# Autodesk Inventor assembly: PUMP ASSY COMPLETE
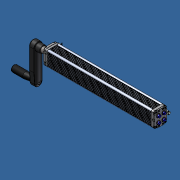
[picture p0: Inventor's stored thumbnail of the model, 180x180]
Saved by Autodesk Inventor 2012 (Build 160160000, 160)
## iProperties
Created: 2013-11
Part Number: PUMP ASSY COMPLETE
Document SubType Name: Assembly
Designer: Admin
Author: Admin
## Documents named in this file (4)
- C:\Andys Backup Data\ANDY'S INVENTOR\INVENTOR LIBRARIES\PARTS LIBRARY\HYDRAULIC VERTICAL ADJUSTMENT\27.9001Telescoping Twin Leg System\PUMP ASSY COMPLETE.iam
- C:\Andys Backup Data\ANDY'S INVENTOR\INVENTOR LIBRARIES\PARTS LIBRARY\HYDRAULIC VERTICAL ADJUSTMENT\27.9001Telescoping Twin Leg System\SUBCOMPONENTS\Qxx18_crank pump\Qxx18_crank.iam
- C:\Andys Backup Data\ANDY'S INVENTOR\INVENTOR LIBRARIES\PARTS LIBRARY\FASTENING ELEMENTS\SCREWS COUNTERSUNK\21.9757 M5x60 CSUNK.ipt
- C:\Andys Backup Data\ANDY'S INVENTOR\INVENTOR LIBRARIES\PARTS LIBRARY\FASTENING ELEMENTS\NUTS\21.1320_2 M5 SQUARE NUT POS FXG.ipt
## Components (7 placed, 3 different names)
1. Qxx18_crank:1 [sub-assembly]
2. 21.9757 M5x60 CSUNK:1
3. 21.9757 M5x60 CSUNK:2
4. 21.9757 M5x60 CSUNK:3
5. 21.1320_2 M5 SQUARE NUT POS FXG:1
6. 21.1320_2 M5 SQUARE NUT POS FXG:2
7. 21.1320_2 M5 SQUARE NUT POS FXG:3
